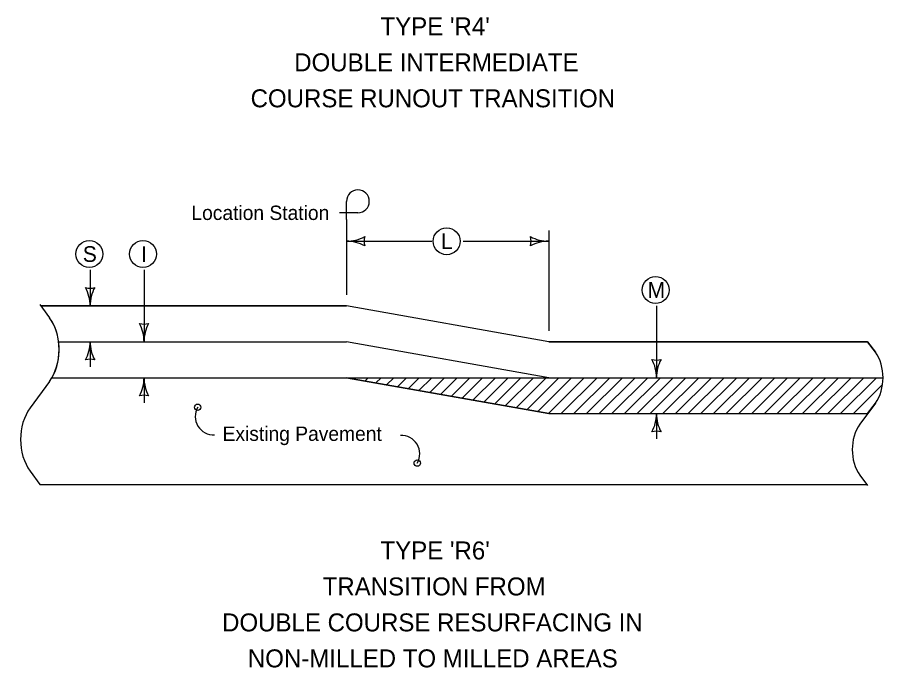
# Model space of a CAD drawing. Extents: x 10133 to 81668, y 2218 to 11018.
# Drawn here: x 20287 to 21253, y 2367 to 3091 of the extents above; entities that cross this region are included whole.
import ezdxf

# ---------------------------------------------------------------- set-up
doc = ezdxf.new("R2010")
doc.units = 0
for name, color, linetype in [('dsnNonPlotable', 7, 'Continuous'), ('dsnStdBlock', 7, 'Continuous'), ('dsnStdBlockNotModified', 7, 'Continuous')]:
    doc.layers.add(name, color=color, linetype=linetype)

msp = doc.modelspace()

# ---------------------------------------------------------------- linework, layer by layer
at = {"layer": 'dsnNonPlotable'}
for p, q in [((20653.3, 2769.84), (20312.94, 2769.84)), ((20312.94, 2769.84), (20322.75, 2756.46)), ((20653.3, 2769.84), (20312.94, 2769.84)), ((20312.94, 2769.84), (20322.75, 2756.46)), ((20878.3, 2729.84), (20653.3, 2769.84)), ((20878.3, 2729.84), (20653.3, 2769.84)), ((21233.3, 2729.84), (20878.3, 2729.84)), ((21233.3, 2729.84), (20878.3, 2729.84)), ((21241.89, 2718.13), (21233.3, 2729.84)), ((21241.89, 2718.13), (21233.3, 2729.84)), ((20325.43, 2689.84), (20653.3, 2689.84)), ((20325.43, 2689.84), (20653.3, 2689.84)), ((20653.3, 2689.84), (20878.3, 2649.84)), ((20653.3, 2689.84), (20878.3, 2649.84)), ((21233.3, 2649.84), (21241.89, 2661.56)), ((21233.3, 2649.84), (21241.89, 2661.56)), ((20878.3, 2649.84), (21233.3, 2649.84)), ((20878.3, 2649.84), (21233.3, 2649.84))]:
    msp.add_line(p, q, dxfattribs=at)
for centre, major_axis, ratio, start_param in [((20296.84, 2721.1), (0, -50), 0.732645, 0.89539), ((20296.84, 2721.1), (0, -50), 0.732645, 0.89539), ((21221.16, 2689.84), (0, -40), 0.73263, 0.785398), ((21221.16, 2689.84), (0, -40), 0.73263, 0.785398)]:
    msp.add_ellipse(centre, major_axis=major_axis, ratio=ratio, start_param=start_param, end_param=2.356194, dxfattribs=at)
at = {"layer": 'dsnStdBlock'}
for p, q in [((20653.3, 2865.6), (20653.3, 2885.92)), ((20653.3, 2865.6), (20653.3, 2885.92)), ((20666, 2873.22), (20645.68, 2873.22)), ((20666, 2873.22), (20645.68, 2873.22)), ((20653.3, 2865.6), (20653.3, 2781.84)), ((20653.3, 2865.6), (20653.3, 2781.84)), ((20878.3, 2853.6), (20878.3, 2741.84)), ((20878.3, 2853.6), (20878.3, 2741.84)), ((20653.3, 2841.6), (20748.3, 2841.6)), ((20653.3, 2841.6), (20748.3, 2841.6)), ((20783.3, 2841.6), (20878.3, 2841.6)), ((20783.3, 2841.6), (20878.3, 2841.6)), ((20367.94, 2809.84), (20367.94, 2769.84)), ((20367.94, 2809.84), (20367.94, 2769.84)), ((20427.94, 2809.84), (20427.94, 2729.84)), ((20427.94, 2809.84), (20427.94, 2729.84)), ((20312.01, 2771.1), (20322.74, 2756.46)), ((20312.01, 2771.1), (20322.74, 2756.46)), ((20312.94, 2769.84), (20653.3, 2769.84)), ((20312.94, 2769.84), (20653.3, 2769.84)), ((20878.3, 2729.84), (20653.3, 2769.84)), ((20878.3, 2729.84), (20653.3, 2769.84)), ((20998.3, 2769.84), (20998.3, 2689.84)), ((20998.3, 2769.84), (20998.3, 2689.84)), ((20332.91, 2729.84), (20653.3, 2729.84)), ((20332.91, 2729.84), (20653.3, 2729.84)), ((20367.94, 2729.84), (20367.94, 2701.84)), ((20367.94, 2729.84), (20367.94, 2701.84)), ((20878.3, 2689.84), (20653.3, 2729.84)), ((20878.3, 2689.84), (20653.3, 2729.84)), ((20878.3, 2729.84), (21233.3, 2729.84)), ((20878.3, 2729.84), (21233.3, 2729.84)), ((21233.3, 2729.84), (21241.88, 2718.13)), ((21233.3, 2729.84), (21241.88, 2718.13)), ((20325.43, 2689.84), (20653.3, 2689.84)), ((20325.43, 2689.84), (20653.3, 2689.84)), ((20427.94, 2689.84), (20427.94, 2661.84)), ((20427.94, 2689.84), (20427.94, 2661.84)), ((20878.3, 2649.84), (20653.3, 2689.84)), ((20653.3, 2689.84), (20878.3, 2689.84)), ((20878.3, 2649.84), (20653.3, 2689.84)), ((20653.3, 2689.84), (20878.3, 2689.84)), ((20661.89, 2688.32), (20663.42, 2689.84)), ((20661.89, 2688.32), (20663.42, 2689.84)), ((20673.9, 2686.18), (20677.56, 2689.84)), ((20673.9, 2686.18), (20677.56, 2689.84)), ((20685.91, 2684.05), (20691.7, 2689.84)), ((20685.91, 2684.05), (20691.7, 2689.84)), ((20697.91, 2681.91), (20705.84, 2689.84)), ((20697.91, 2681.91), (20705.84, 2689.84)), ((20709.92, 2679.78), (20719.99, 2689.84)), ((20709.92, 2679.78), (20719.99, 2689.84)), ((20721.93, 2677.64), (20734.13, 2689.84)), ((20721.93, 2677.64), (20734.13, 2689.84)), ((20733.94, 2675.51), (20748.27, 2689.84)), ((20733.94, 2675.51), (20748.27, 2689.84)), ((20745.94, 2673.37), (20762.41, 2689.84)), ((20745.94, 2673.37), (20762.41, 2689.84)), ((20757.95, 2671.24), (20776.55, 2689.84)), ((20757.95, 2671.24), (20776.55, 2689.84)), ((20769.96, 2669.1), (20790.7, 2689.84)), ((20769.96, 2669.1), (20790.7, 2689.84)), ((20781.97, 2666.97), (20804.84, 2689.84)), ((20781.97, 2666.97), (20804.84, 2689.84)), ((20793.97, 2664.83), (20818.98, 2689.84)), ((20793.97, 2664.83), (20818.98, 2689.84)), ((20805.98, 2662.7), (20833.12, 2689.84)), ((20805.98, 2662.7), (20833.12, 2689.84)), ((20817.99, 2660.56), (20847.27, 2689.84)), ((20817.99, 2660.56), (20847.27, 2689.84)), ((20830, 2658.43), (20861.41, 2689.84)), ((20830, 2658.43), (20861.41, 2689.84)), ((20842, 2656.3), (20875.55, 2689.84)), ((20842, 2656.3), (20875.55, 2689.84)), ((20854.01, 2654.16), (20889.69, 2689.84)), ((20854.01, 2654.16), (20889.69, 2689.84)), ((20866.02, 2652.03), (20903.83, 2689.84)), ((20866.02, 2652.03), (20903.83, 2689.84)), ((20878.03, 2649.89), (20917.98, 2689.84)), ((20878.03, 2649.89), (20917.98, 2689.84)), ((20878.3, 2689.84), (21250.47, 2689.84)), ((20878.3, 2689.84), (21250.47, 2689.84)), ((20892.12, 2649.84), (20932.12, 2689.84)), ((20892.12, 2649.84), (20932.12, 2689.84)), ((20906.26, 2649.84), (20946.26, 2689.84)), ((20906.26, 2649.84), (20946.26, 2689.84)), ((20920.4, 2649.84), (20960.4, 2689.84)), ((20920.4, 2649.84), (20960.4, 2689.84)), ((20934.54, 2649.84), (20974.54, 2689.84)), ((20934.54, 2649.84), (20974.54, 2689.84)), ((20948.69, 2649.84), (20988.69, 2689.84)), ((20948.69, 2649.84), (20988.69, 2689.84)), ((20962.83, 2649.84), (21002.83, 2689.84)), ((20962.83, 2649.84), (21002.83, 2689.84)), ((20976.97, 2649.84), (21016.97, 2689.84)), ((20976.97, 2649.84), (21016.97, 2689.84)), ((20991.11, 2649.84), (21031.11, 2689.84)), ((20991.11, 2649.84), (21031.11, 2689.84)), ((21005.26, 2649.84), (21045.26, 2689.84)), ((21005.26, 2649.84), (21045.26, 2689.84)), ((21019.4, 2649.84), (21059.4, 2689.84)), ((21019.4, 2649.84), (21059.4, 2689.84)), ((21033.54, 2649.84), (21073.54, 2689.84)), ((21033.54, 2649.84), (21073.54, 2689.84)), ((21047.68, 2649.84), (21087.68, 2689.84)), ((21047.68, 2649.84), (21087.68, 2689.84)), ((21061.82, 2649.84), (21101.82, 2689.84)), ((21061.82, 2649.84), (21101.82, 2689.84)), ((21075.97, 2649.84), (21115.97, 2689.84)), ((21075.97, 2649.84), (21115.97, 2689.84)), ((21090.11, 2649.84), (21130.11, 2689.84)), ((21090.11, 2649.84), (21130.11, 2689.84)), ((21104.25, 2649.84), (21144.25, 2689.84)), ((21104.25, 2649.84), (21144.25, 2689.84)), ((21118.39, 2649.84), (21158.39, 2689.84)), ((21118.39, 2649.84), (21158.39, 2689.84)), ((21132.53, 2649.84), (21172.53, 2689.84)), ((21132.53, 2649.84), (21172.53, 2689.84)), ((21146.68, 2649.84), (21186.68, 2689.84)), ((21146.68, 2649.84), (21186.68, 2689.84)), ((21160.82, 2649.84), (21200.82, 2689.84)), ((21160.82, 2649.84), (21200.82, 2689.84)), ((21174.96, 2649.84), (21214.96, 2689.84)), ((21174.96, 2649.84), (21214.96, 2689.84)), ((21189.1, 2649.84), (21229.1, 2689.84)), ((21189.1, 2649.84), (21229.1, 2689.84)), ((21203.25, 2649.84), (21243.25, 2689.84)), ((21203.25, 2649.84), (21243.25, 2689.84)), ((20322.74, 2685.74), (20301.29, 2656.46)), ((20322.74, 2685.74), (20301.29, 2656.46)), ((21217.39, 2649.84), (21249.96, 2682.41)), ((21217.39, 2649.84), (21249.96, 2682.41)), ((21241.88, 2661.55), (21224.72, 2638.13)), ((21241.88, 2661.55), (21224.72, 2638.13)), ((20878.3, 2649.84), (21233.3, 2649.84)), ((20878.3, 2649.84), (21233.3, 2649.84)), ((20998.3, 2649.84), (20998.3, 2621.84)), ((20998.3, 2649.84), (20998.3, 2621.84)), ((20301.29, 2585.74), (20312.01, 2571.1)), ((20301.29, 2585.74), (20312.01, 2571.1)), ((21224.72, 2581.55), (21233.3, 2569.84)), ((21224.72, 2581.55), (21233.3, 2569.84)), ((20312.01, 2571.1), (21232.45, 2571.1)), ((20312.01, 2571.1), (21232.45, 2571.1))]:
    msp.add_line(p, q, dxfattribs=at)
for centre, radius in [((20764.81, 2841.6), 15), ((20764.81, 2841.6), 15), ((20367.1, 2827.34), 15), ((20367.1, 2827.34), 15), ((20426.77, 2827.34), 15), ((20426.77, 2827.34), 15), ((20997.3, 2787.34), 15), ((20997.3, 2787.34), 15), ((20487.7, 2656.95), 3.56), ((20487.7, 2656.95), 3.56), ((20732.06, 2594.9), 3.56), ((20732.06, 2594.9), 3.56)]:
    msp.add_circle(centre, radius, dxfattribs=at)
for centre, radius, start, end in [((20666, 2885.92), 12.7, 270, 180), ((20666, 2885.92), 12.7, 270, 180), ((20653.3, 2884.78), 43.18, 270, 298.07249), ((20653.3, 2884.78), 43.18, 270, 298.07249), ((20653.3, 2798.42), 43.18, 61.92751, 90), ((20653.3, 2798.42), 43.18, 61.92751, 90), ((20689.51, 2841.6), 16.68, 162.26665, 197.73335), ((20689.51, 2841.6), 16.68, 162.26665, 197.73335), ((20842.1, 2841.6), 16.68, 342.26665, 17.73335), ((20878.3, 2884.78), 43.18, 241.92751, 270), ((20842.1, 2841.6), 16.68, 342.26665, 17.73335), ((20878.3, 2884.78), 43.18, 241.92751, 270), ((20878.3, 2798.42), 43.18, 90, 118.07249), ((20878.3, 2798.42), 43.18, 90, 118.07249), ((20367.94, 2806.05), 16.68, 252.26665, 287.73335), ((20324.76, 2769.84), 43.18, 360, 28.07249), ((20367.94, 2806.05), 16.68, 252.26665, 287.73335), ((20324.76, 2769.84), 43.18, 360, 28.07249), ((20411.12, 2769.84), 43.18, 151.92751, 180), ((20411.12, 2769.84), 43.18, 151.92751, 180), ((20427.94, 2766.05), 16.68, 252.26665, 287.73335), ((20384.76, 2729.84), 43.18, 360, 28.07249), ((20427.94, 2766.05), 16.68, 252.26665, 287.73335), ((20384.76, 2729.84), 43.18, 360, 28.07249), ((20471.12, 2729.84), 43.18, 151.92751, 180), ((20471.12, 2729.84), 43.18, 151.92751, 180), ((20324.76, 2729.84), 43.18, 331.92751, 360), ((20324.76, 2729.84), 43.18, 331.92751, 360), ((20411.12, 2729.84), 43.18, 180, 208.07249), ((20411.12, 2729.84), 43.18, 180, 208.07249), ((20367.94, 2693.64), 16.68, 72.26665, 107.73335), ((20367.94, 2693.64), 16.68, 72.26665, 107.73335), ((20998.3, 2726.05), 16.68, 252.26665, 287.73335), ((20955.12, 2689.84), 43.18, 360, 28.07249), ((20998.3, 2726.05), 16.68, 252.26665, 287.73335), ((20955.12, 2689.84), 43.18, 360, 28.07249), ((21041.48, 2689.84), 43.18, 151.92751, 180), ((21041.48, 2689.84), 43.18, 151.92751, 180), ((20384.76, 2689.84), 43.18, 331.92751, 360), ((20384.76, 2689.84), 43.18, 331.92751, 360), ((20471.12, 2689.84), 43.18, 180, 208.07249), ((20471.12, 2689.84), 43.18, 180, 208.07249), ((20427.94, 2653.64), 16.68, 72.26665, 107.73335), ((20427.94, 2653.64), 16.68, 72.26665, 107.73335), ((20505.42, 2646.75), 20.45, 150.06834, 272.84357), ((20505.42, 2646.75), 20.45, 150.06834, 272.84357), ((20955.12, 2649.84), 43.18, 331.92751, 360), ((20955.12, 2649.84), 43.18, 331.92751, 360), ((21041.48, 2649.84), 43.18, 180, 208.07249), ((21041.48, 2649.84), 43.18, 180, 208.07249), ((20998.3, 2613.64), 16.68, 72.26665, 107.73335), ((20998.3, 2613.64), 16.68, 72.26665, 107.73335), ((20714.34, 2605.1), 20.45, 330.06834, 92.84357), ((20714.34, 2605.1), 20.45, 330.06834, 92.84357)]:
    msp.add_arc(centre, radius, start, end, dxfattribs=at)
for centre, major_axis, ratio in [((20296.84, 2721.1), (0, -50), 0.732645), ((20296.84, 2721.1), (0, -50), 0.732645), ((21221.16, 2689.84), (0, -40), 0.73263), ((21221.16, 2689.84), (0, -40), 0.73263), ((20327.19, 2621.1), (0, 50), 0.732645), ((20327.19, 2621.1), (0, 50), 0.732645), ((21245.44, 2609.84), (0, 40), 0.73263), ((21245.44, 2609.84), (0, 40), 0.73263)]:
    msp.add_ellipse(centre, major_axis=major_axis, ratio=ratio, start_param=0.785398, end_param=2.356194, dxfattribs=at)

# ---------------------------------------------------------------- texts
at = {"layer": 'dsnStdBlockNotModified'}
for s, height, p in [("TYPE 'R4'", 20, (20691.11, 3070.53)), ("TYPE 'R4'", 20, (20691.11, 3070.53)), (' DOUBLE INTERMEDIATE ', 20, (20587.68, 3030.53)), (' DOUBLE INTERMEDIATE ', 20, (20587.68, 3030.53)), ('COURSE RUNOUT TRANSITION', 20, (20546.56, 2990.53)), ('COURSE RUNOUT TRANSITION', 20, (20546.56, 2990.53)), ('Location Station', 16, (20480.68, 2865.22)), ('Location Station', 16, (20480.68, 2865.22)), ('L', 17.5, (20758.54, 2832.85)), ('L', 17.5, (20758.54, 2832.85)), ('S', 17.5, (20359.83, 2818.59)), ('S', 17.5, (20359.83, 2818.59)), ('I', 17.5, (20424.62, 2818.59)), ('I', 17.5, (20424.62, 2818.59)), ('M', 17.5, (20988.38, 2778.59)), ('M', 17.5, (20988.38, 2778.59)), ('Existing Pavement', 16, (20515.38, 2619.56)), ('Existing Pavement', 16, (20515.38, 2619.56)), ("TYPE 'R6'", 20, (20691.11, 2487.71)), ("TYPE 'R6'", 20, (20691.11, 2487.71)), ('TRANSITION FROM', 20, (20626.75, 2447.71)), ('TRANSITION FROM', 20, (20626.75, 2447.71)), ('DOUBLE COURSE RESURFACING IN', 20, (20514.84, 2407.71)), ('DOUBLE COURSE RESURFACING IN', 20, (20514.84, 2407.71)), ('NON-MILLED TO MILLED AREAS', 20, (20543.51, 2367.71)), ('NON-MILLED TO MILLED AREAS', 20, (20543.51, 2367.71))]:
    msp.add_text(s, height=height, dxfattribs=at).set_placement(p)

doc.saveas('drawing.dxf')
